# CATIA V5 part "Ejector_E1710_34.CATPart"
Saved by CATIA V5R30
Part number: Vyhazovac_7x160_10
Nomenclature: E1710/7x160
Description: MEUSBURGER
Property "Material": "1.221"
Publications: "__DrillHole", "Base"
Bounding box of the stored display mesh (mm): x -5.992 to 5.992, y -5.992 to 5.992, z 0 to 152
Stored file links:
  E:\Bakalarka\Model\Forma_v7\Ejector_E1710_34.CATPart
  E:\dev\MoldDesign\intel_a\startup\components\MoldCatalog\Ejector\Meusburger\Ejector_E1710\TableE1710.txt
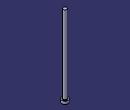
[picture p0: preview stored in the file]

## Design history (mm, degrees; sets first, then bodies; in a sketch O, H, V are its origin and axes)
Parameters
  Ref = "E1710/7x160" {design table}
  D1 = 7 mm {design table}
  D3 = 12 mm {design table}
  L = 160 mm {design table}
  L3 = 5 mm {design table}
  R = 0.5 mm {design table}
  k_d3 = 13 mm {design table}
  k_d1 = 7.2 mm {design table}
  k_F = 0.5 mm {design table}
  kl = 17 mm {design table}
  Mat = "1.221" {design table}
  HeatTreat = "ISO6751" {design table}
  Offset_Parting = 10 mm
  Anti_Rotation = "Normal"
  Anti_Rotation_D = 4 mm
  Anti_Rotation_D_Icut = 4 mm
  Add_Length_L = 1.3377 mm
  Add_Length_D3 = 0 mm
  SupplierRef = "Meusburger 2017"
  BmpRef = "F_MldEjectorD1"
  DrillHole_Length = 225 mm
  ValidationTest = false
  Anti_Rotation_D_min = 4 mm {= OffSet_D1 /2}
  Anti_Rotation_D_max = 5.925 mm {= D3/2-0.075mm}
  Anti_Rotation_D_ref = 4 mm {= Anti_Rotation_D}
  Anti_Rotation_D_Icut_ref = 4 mm {= Anti_Rotation_D_Icut}
  Anti_Rotation_Ref_Icut = 2.3246 mm
  Offset_L = 20 mm
  D = 7 mm {= D1}
  OffSet_D1 = 8 mm {= D1+2*R}
  OffSet_D3 = 13 mm {= D3+1mm}
  XG_Split = 95 mm
  YG_Split = 44.5 mm
  ZG_Split = -198 mm
  DirX_Split = 0 mm
  DirY_Split = 0 mm
  DirZ_Split = 1 mm
Set1 "BaseBody"
  Point1 "Base": (0, 0, 0)
  Plane1: type Offset, RefPlane xy-plane, Offset 225 {= DrillHole_Length}, reversed
  Sketch1 "Sketch.2" on xy-plane, origin (0, 0, 0), H (1, 0, 0), V (0, 1, 0)
    point P1 (-0.46, 1.1623)
    point P2 (0.46, 1.1623)
    construction line L1 (-0.46, 1.1623) -> (0.46, 1.1623)
    point P3 (0.46, -1.1623)
    line L2 (0.46, -1.1623) -> (0.46, 1.1623)
    point P4 (-0.46, -1.1623)
    construction line L3 (0.46, -1.1623) -> (-0.46, -1.1623)
    line L4 (-0.46, 1.1623) -> (-0.46, -1.1623)
    point P5 (-0.21, 1.1623)
    arc A1 centre (-0.21, 1.1623) radius 0.25 from (-0.21, 1.4123) to (-0.46, 1.1623) ccw
    point P7 (0.21, 1.1623)
    point P8 (0.21, 1.4123)
    arc A2 centre (0.21, 1.1623) radius 0.25 from (0.46, 1.1623) to (0.21, 1.4123) ccw
    line L5 (-0.21, 1.4123) -> (0.21, 1.4123)
    point P9 (-0.46, -1.1623)
    arc A3 centre (-0.21, -1.1623) radius 0.25 from (-0.46, -1.1623) to (-0.21, -1.4123) ccw
    point P11 (0.21, -1.4123)
    line L6 (-0.21, -1.4123) -> (0.21, -1.4123)
    point P12 (0.46, -1.1623)
    arc A4 centre (0.21, -1.1623) radius 0.25 from (0.21, -1.4123) to (0.46, -1.1623) ccw
    point P14 (-0.46, 1.1623)
    point P15 (-0.46, -1.1623)
    point P16 (0.46, 1.1623)
    point P17 (0.46, -1.1623)
    reference projected circle E1 centre (0, 0) radius 1.25 from edge [face of Shaft1 from Sketch2.L3 | face of Shaft1 from Sketch2.L4]
    reference projected circle E2 centre (0, 0) radius 1.25 from edge [face of Shaft1 from Sketch2.L3 | face of Shaft1 from Sketch2.L4]
    reference projected circle E3 centre (0, 0) radius 1.25 from edge [face of Shaft1 from Sketch2.L3 | face of Shaft1 from Sketch2.L4]
    reference projected circle E4 centre (0, 0) radius 1.25 from edge [face of Shaft1 from Sketch2.L3 | face of Shaft1 from Sketch2.L4]
    point P18 (-0.46, -1.1623)
    point P19 (-0.21, -1.4123)
    point P20 (0.21, -1.4123)
    point P21 (0.46, -1.1623)
    point P22 (-0.21, -1.4123)
    point P23 (0.21, -1.4123)
    distance P14 P15 = 2.3246 (reference)
    distance P16 P17 = 2.3246 (reference)
    distance L1 P14 = 0 (reference)
    radius A1 = 3.5
    distance L4 V = 4.01
    distance L2 V = 5.935
    distance L5 L6 = 12
    horizontal: L1 H, L3 H, L5 H
    vertical: L2 V, L4 V
    coincidence: P5 L1, P7 L1, P3 P12, P14 L4, P15 L4, P16 L2, P17 L2, P14 E1, P15 E2, P16 E3, P17 E4, P3 P21, P4 P18, P20 P23, P19 P22
    tangency: A1 L4, A2 L2, A2 L5, A1 L5
    symmetry: P1 P9 H, A1 A3 H, P8 P11 H, L5 L6 H, P2 P12 H, A2 A4 H
  DatumSurface1
Body1 "PartBody" (main body)
  Sketch2 "Sketch.1" on zx-plane, origin (0, 0, 0), H (-1, 0, 0), V (0, 0, 1)
    point P1 (0, 160)
    line L1 (3.5, 160) -> (0, 160)
    line L2 (3.5, 5) -> (3.5, 160)
    line L3 (6, 5) -> (3.5, 5)
    line L4 (6, 0) -> (6, 5)
    point P5 (0, 0)
    line L5 (0, 0) -> (6, 0)
    point P6 (0, 160)
    axis line L6 (0, 160) -> (0, 0)
    point P7 (0, 0)
    point P8 (3.5, 5)
    point P9 (3.5, 5)
    line L7 (0, 160) -> (0, 0)
    distance L5 L3 = 5 {= L3}
    distance L5 L1 = 160 {= L}
    distance L2 L6 = 3.5 {= D1 /2}
    distance L4 L6 = 6 {= D3 /2}
    coincidence: L6 P5, P1 L6, L5 H, L6 V, P7 O, P6 P1, P8 P9
    vertical: L2 V, L7 V
    horizontal: L1 H
  Shaft1 "Shaft.1": profile Sketch2, axis Sketch2.L6, angle 360
  Pocket1 "Pocket.1": profile Sketch1, direction (0, 0, 1), length 6, outer side, deactivated
  Pocket2 "Pocket.2": profile Sketch1, direction (0, 0, 1), length 6, outer side, deactivated
  Fillet1: radius 0.5 {= R}, on edge [face of Shaft1 from Sketch2.L2 | face of Shaft1 from Sketch2.L3]
  Pocket3: profile face of Shaft1 from Sketch2.L1, direction along face of Shaft1 from Sketch2.L1 reversed, up to face of DatumSurface1
Body2 "__DrillHole"
  Sketch3 "Sketch.3" on face of Shaft1, origin (0, 0, 0), H (1, 0, 0), V (0, -1, 0)
    point P1 (0, 0)
    reference projected point E1 (0, 0) from Point1
    coincidence: E1 P1
  Hole1 "Hole.1": placed by Sketch3, at (0, 0, 0) direction (0, 0, 1), diameter 8 {= OffSet_D1}, depth 140 {= L-Offset_L}
  Sketch4 "Sketch.4" on face of Shaft1, origin (0, 0, 0), H (1, 0, 0), V (0, -1, 0)
    point P1 (0, 0)
    reference projected point E1 (0, 0) from Point1
    coincidence: E1 P1
  Hole2 "Hole.2": placed by Sketch4, at (0, 0, 0) direction (0, 0, 1), diameter 7 {= D1}, depth 160 {= L}
  Sketch5 "Sketch.5" on face of Shaft1 from Sketch2.L3, origin (0, 0, 5), H (1, 0, 0), V (0, 1, 0)
    point P1 (0, 0)
    reference projected point E1 (0, 0) from Point1
    coincidence: E1 P1
  Hole3 "Hole.3": placed by Sketch5, at (0, 0, 5) direction (0, 0, -1), diameter 13 {= OffSet_D3}, depth 230 {= L3 +DrillHole_Length}
  Chamfer1: length 0.5 {= k_F}, angle 45, on edge [face of Hole1 | face of Hole3]
  Body3 "__Body.1"
    Pocket4 "Pocket.3": profile Sketch1, direction (0, 0, -1), length 225, opposite side length 5, deactivated
  Assemble1: tool Body3
  Chamfer2: length 0.5 {= k_F}, angle 45, on edge [start face of Pocket4 | face of Hole1], deactivated
  Body4 "__Body.2"
    Pocket5 "Pocket.4": profile Sketch1, direction (0, 0, -1), length 225, opposite side length 5, deactivated
  Assemble2: tool Body4
  Chamfer3: length 0.5 {= k_F}, angle 45, on edge [start face of Pocket5 | face of Hole1], deactivated
Relations
  design table "TableE1710", configuration 278, drives Ref, D1, D3, L, L3, R, k_d3, k_d1, k_F, kl, Mat, HeatTreat
  Offset_L = 20mm (deactivated)
  rule "Cut_Head_rule":
    let sketch_cut (length)
    let PartBody_Pocket_Sketch (Boolean)
    let I_PartBody_Pocket (Boolean)
    let D_PartBody_Pocket (Boolean)
    let N_DrillHole_Hole (Boolean)
    let N_DrillHole_Hole_Sketch (Boolean)
    let I_DrillHole_Pocket (Boolean)
    let D_DrillHole_Pocket (Boolean)
    /* --------------------------------------------------------------------------------------*/
    if Anti_Rotation =="Normal"
    {
    	sketch_cut=Anti_Rotation_D_max
    	PartBody_Pocket_Sketch = false
    	I_PartBody_Pocket = false
    	D_PartBody_Pocket = false
    	N_DrillHole_Hole = true
    	N_DrillHole_Hole_Sketch = true
    	I_DrillHole_Pocket = false
    	D_DrillHole_Pocket = false
    	Chamfer1.Activity= true
    	Chamfer2.Activity= false
    	Chamfer3.Activity= false
    }
    if Anti_Rotation == "I_Cut"
    {
    	sketch_cut=Anti_Rotation_D_Icut_ref
    	PartBody_Pocket_Sketch = true
    	I_PartBody_Pocket = true
    	D_PartBody_Pocket = false
    	N_DrillHole_Hole = false
    	N_DrillHole_Hole_Sketch = false
    	I_DrillHole_Pocket = true
    	D_DrillHole_Pocket = false
    	Chamfer1.Activity= false
    	Chamfer2.Activity= true
    	Chamfer3.Activity= false
    }
    if Anti_Rotation =="D_Cut"
    {
    	sketch_cut=Anti_Rotation_D_max
    	PartBody_Pocket_Sketch = true
    	I_PartBody_Pocket = false
    	D_PartBody_Pocket = true
    	N_DrillHole_Hole = false
    	N_DrillHole_Hole_Sketch = false
    	I_DrillHole_Pocket = false
    	D_DrillHole_Pocket = true
    	Chamfer1.Activity= false
    	Chamfer2.Activity= false
    	Chamfer3.Activity= true
    }
    /* --------------------------------------------------------------------------------------*/
    Sketch1.distance(L2 V) = sketch_cut+0.01mm
    Sketch1.distance(L4 V) =Anti_Rotation_D_ref+0.01mm
    Sketch1.radius(A1) =D/2
    Pocket4.FirstLimit.Depth = DrillHole_Length
    Pocket5.FirstLimit.Depth = DrillHole_Length
    Pocket1.FirstLimit.Depth = L3+1mm
    Pocket2.FirstLimit.Depth = L3+1mm
    Pocket4.SecondLimit.Depth = L3
    Pocket5.SecondLimit.Depth =L3
    Pocket1.Activity = I_PartBody_Pocket
    Pocket2.Activity = D_PartBody_Pocket
    Sketch1.Activity =PartBody_Pocket_Sketch
    Hole3.Activity= N_DrillHole_Hole
    Sketch5.Activity = N_DrillHole_Hole_Sketch
    Pocket4.Activity = I_DrillHole_Pocket
    Pocket5.Activity  = D_DrillHole_Pocket
  rule "Anti_Rotation_Icut_constrain":
    let Ref1(length)
    let Ref2(length)
    let Ref3(length)
    let Diam1(length)
    let Diam2(length)
    let Add_Length_Lmin (length)
    Ref1=Sketch1.distance(P14 P15)
    Ref2=Sketch1.distance(P16 P17)
    Diam1=D
    Diam2=D3
    /* --------------------------------------------------------------------*/
    if Ref1 >Ref2
    	Anti_Rotation_Ref_Icut = Ref1
    else
    	Anti_Rotation_Ref_Icut  =Ref2
    Add_Length_D3 .InferiorRange=Anti_Rotation_Ref_Icut /2+Diam1/2 -Diam2/2
    if Add_Length_D3 .InferiorRange<0mm
    	Add_Length_D3 .InferiorRange=0mm
    if ValidationTest == "true"
    	Ref3   = 2*Add_Length_L +Anti_Rotation_Ref_Icut  +2*Diam1/2
    else
    	Ref3  =Diam2+2*Add_Length_D3
    if Ref3 <Diam2
    {
    	Ref3 =Diam2
    }
    /* --------------------------------------------------------------------*/
    Sketch1.distance(L5 L6) = Ref3
    Add_Length_L .InferiorRange=Diam2/2-Anti_Rotation_Ref_Icut/2-Diam1/2
    Add_Length_Lmin=Diam2/2-Anti_Rotation_Ref_Icut/2-Diam1/2
    if Add_Length_Lmin<0mm
    	Add_Length_L .InferiorRange=0mm
    else
    	Add_Length_L .InferiorRange=Add_Length_Lmin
